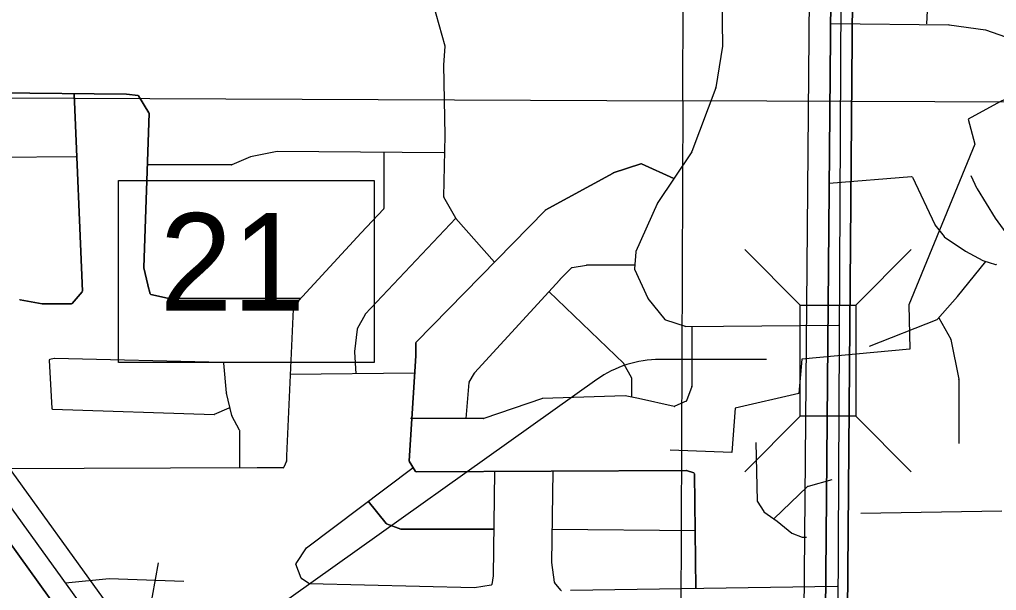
# Model space of a CAD drawing. Extents: x 408847 to 817539, y 923858 to 1151780.
# Drawn here: x 490719 to 495222, y 1058236 to 1060869 of the extents above; entities that cross this region are included whole.
import ezdxf

# ---------------------------------------------------------------- set-up
doc = ezdxf.new("R2010")
doc.units = 0
for name, color, linetype in [('Bridges', 7, 'Continuous'), ('County Route Divided Highway Outline and Fill', 7, 'Continuous'), ('County Routes Highway Center Lines', 7, 'Continuous'), ('Level 43', 7, 'Continuous'), ('Level 6', 7, 'Continuous'), ('Local Roads Improved', 7, 'Continuous'), ('Local Roads Paved', 7, 'Continuous'), ('Narrow River Creek and Branch and Slough', 7, 'Continuous'), ('Quad Borders', 7, 'Continuous'), ('Section Lines', 7, 'Continuous'), ('US Route Divided Highway Outline and Fill', 7, 'Continuous'), ('US Routes Highway Center Lines', 7, 'Continuous')]:
    doc.layers.add(name, color=color, linetype=linetype)

msp = doc.modelspace()

# ---------------------------------------------------------------- linework, layer by layer
at = {"layer": 'Bridges'}
for p, q in [((494317.6, 1059551.6), (494061.6, 1059807.6)), ((494573.6, 1059551.6), (494829.6, 1059807.6)), ((494317.6, 1059039.6), (494061.6, 1058783.6)), ((494573.6, 1059039.6), (494829.6, 1058783.6)), ((491295.8, 1058008.1), (491358.9, 1058364.5))]:
    msp.add_line(p, q, dxfattribs=at)
msp.add_lwpolyline([(494317.6, 1059039.6), (494317.6, 1059551.6), (494573.6, 1059551.6), (494573.6, 1059039.6)], close=True, dxfattribs=at)
at = {"layer": 'County Route Divided Highway Outline and Fill'}
for p, q in [((494505.3, 1078336), (494302.9, 1054340.5)), ((494605.3, 1078335.2), (494402.6, 1054313.9)), ((494705.3, 1078334.3), (494502.5, 1054302.3)), ((494502.5, 1054302.3), (494705.3, 1078334.3))]:
    msp.add_line(p, q, dxfattribs=at)
at = {"layer": 'County Routes Highway Center Lines'}
msp.add_line((494402.6, 1054313.9), (494605.3, 1078335.2), dxfattribs=at)
at = {"layer": 'Level 43'}
msp.add_lwpolyline([(491174.7, 1060126.5), (492354, 1060126.5), (492354, 1059287.4), (491174.7, 1059287.4)], close=True, dxfattribs=at)
at = {"layer": 'Level 6'}
for p, q in [((491636.7, 1057465.4), (489350, 1060629.5)), ((489186.2, 1060514.5), (491474.6, 1057348.2))]:
    msp.add_line(p, q, dxfattribs=at)
at = {"layer": 'Local Roads Improved'}
for p, q in [((493142.2, 1059989.3), (493454.9, 1060161)), ((493455.5, 1060161.3), (493582.8, 1060203.7)), ((493585.7, 1060203.6), (493734.9, 1060135.2)), ((492546.6, 1059381.4), (493141.3, 1059988.6)), ((492545.5, 1059318.9), (492545.5, 1059378.6)), ((492514.9, 1058834.2), (492545.5, 1059318.6)), ((492544.3, 1058785.6), (492515.5, 1058831.8)), ((492042, 1058433.6), (492533.1, 1058803.7)), ((493792.6, 1058789.9), (492547.7, 1058783.7)), ((492908.3, 1058785.5), (492902, 1058304.3)), ((493172.5, 1058365.9), (493178.9, 1058786.9)), ((493827.4, 1058778.5), (493793.9, 1058789.7)), ((493836.5, 1058245.1), (493830.2, 1058774.7)), ((492409.6, 1058544.8), (492326, 1058647.7)), ((492477.2, 1058519.6), (492411.3, 1058543.5)), ((492904.8, 1058519.3), (492478.6, 1058519.3)), ((491993.4, 1058361.1), (492041.1, 1058432.7)), ((493184.6, 1058274.5), (493172.5, 1058365.3)), ((492016.5, 1058293), (491993, 1058357.5)), ((492052.8, 1058267.8), (492018, 1058291.1)), ((492902, 1058303.8), (492896.3, 1058264)), ((493214.3, 1058237.9), (493185.5, 1058272.5)), ((492815.6, 1058248.8), (492054.9, 1058267.2)), ((492892.9, 1058260.6), (492816.3, 1058248.8)), ((494487.8, 1058254.9), (493258.5, 1058236.4))]:
    msp.add_line(p, q, dxfattribs=at)
for centre, start, end in [((493456.8, 1060157.5), 108.443, 118.7789), ((493584, 1060199.9), 65.3663, 108.443), ((493144.2, 1059985.8), 118.7789, 135.598), ((492549.5, 1059378.6), 135.598, 180), ((492541.5, 1059318.9), 356.3802, 0), ((492518.8, 1058834), 176.3802, 211.9934), ((492547.7, 1058787.7), 211.9934, 270.2824), ((493792.6, 1058785.9), 71.557, 90.2824), ((493826.2, 1058774.7), 0.69, 71.557), ((492412.7, 1058547.3), 219.0808, 250.0083), ((492478.6, 1058523.3), 250.0083, 270), ((492044.4, 1058430.4), 127.0016, 146.3223), ((491996.8, 1058358.9), 146.3223, 199.9745), ((493176.5, 1058365.8), 179.119, 187.5911), ((492020.2, 1058294.4), 199.9745, 236.2976), ((492898, 1058304.4), 351.8736, 359.2465), ((493188.6, 1058275), 187.5911, 219.7924), ((492055, 1058271.2), 236.2976, 268.6134), ((492815.7, 1058252.7), 268.6134, 278.7502), ((492892.3, 1058264.5), 278.7502, 351.8736), ((493217.3, 1058240.4), 219.7924, 270), ((493258.5, 1058240.4), 270, 270.8598)]:
    msp.add_arc(centre, 4, start, end, dxfattribs=at)
at = {"layer": 'Local Roads Paved'}
for p, q in [((493953.1, 1061126.6), (493959.2, 1060745.7)), ((493953.1, 1061126.6), (493959.2, 1060745.7)), ((494900.5, 1060849.3), (494914.3, 1061083.8)), ((492680.5, 1060746.1), (492625.5, 1060941.8)), ((494457.8, 1060849.9), (495003, 1060844.6)), ((495003.5, 1060844.6), (495170.9, 1060821.3)), ((495171.7, 1060821.1), (495344, 1060760.6)), ((492674.6, 1060659.5), (492680.7, 1060744.7)), ((493959.1, 1060745), (493928.5, 1060555.1)), ((493959.1, 1060745), (493928.5, 1060555.1)), ((492680.7, 1060333.5), (492674.6, 1060659.1)), ((491211.5, 1060524), (490081.9, 1060536.3)), ((490081.9, 1060536.3), (491211.5, 1060524)), ((491008.8, 1059615.5), (490971.6, 1060526.6)), ((490971.6, 1060526.6), (491008.8, 1059615.5)), ((491265.1, 1060518.1), (491211.9, 1060524)), ((491211.9, 1060524), (491265.1, 1060518.1)), ((493928.3, 1060554.4), (493818, 1060260)), ((493928.3, 1060554.4), (493818, 1060260)), ((491315.6, 1060438.9), (491268.1, 1060516.2)), ((491268.1, 1060516.2), (491315.6, 1060438.9)), ((491291.6, 1059725.1), (491316.2, 1060436.7)), ((491316.2, 1060436.7), (491291.6, 1059725.1)), ((492674.6, 1060051.6), (492680.7, 1060333.3)), ((491905.9, 1060259.5), (491783.8, 1060235.1)), ((492674.6, 1060253.4), (491906.7, 1060259.6)), ((492398, 1060255.6), (492398, 1059996.7)), ((493817.6, 1060259.2), (493658.2, 1060020)), ((493817.6, 1060259.2), (493658.2, 1060020)), ((490978.2, 1060235), (490076.7, 1060228.9)), ((491783, 1060234.8), (491698, 1060198.4)), ((491696.5, 1060198.1), (491307.9, 1060198.1)), ((493454.9, 1060161), (493142.2, 1059989.3)), ((493582.8, 1060203.7), (493455.5, 1060161.3)), ((493734.9, 1060135.2), (493585.7, 1060203.6)), ((494451.6, 1060114.5), (494830.5, 1060144.2)), ((494834.4, 1060141.9), (494937.5, 1059923.4)), ((495133.9, 1060088), (495106, 1060148.5)), ((495218, 1059952.4), (495134.1, 1060087.5)), ((492729.7, 1059952.5), (492675.1, 1060049.5)), ((492396.9, 1059994), (492293.5, 1059884.5)), ((493141.3, 1059988.6), (492546.6, 1059381.4)), ((493657.9, 1060019.4), (493560, 1059799)), ((493657.9, 1060019.4), (493560, 1059799)), ((492729.6, 1059952.6), (492312.3, 1059509.7)), ((492907.9, 1059750.3), (492730.2, 1059951.8)), ((495291.2, 1059851.6), (495218.1, 1059952.1)), ((494938, 1059922.7), (494980.4, 1059868.2)), ((492293.5, 1059884.5), (492004.8, 1059571.1)), ((494981.3, 1059867.3), (495078.9, 1059800.2)), ((493559.6, 1059797.7), (493553.6, 1059719.5)), ((493559.6, 1059797.7), (493553.6, 1059719.5)), ((495079.3, 1059799.9), (495158.6, 1059757.2)), ((495159.4, 1059756.9), (495218.4, 1059739.2)), ((491310, 1059644.7), (491291.7, 1059724.1)), ((491291.7, 1059724.1), (491310, 1059644.7)), ((493209.4, 1059669.3), (493263.8, 1059723.7)), ((493265.9, 1059724.8), (493331.9, 1059736.8)), ((493332.6, 1059736.9), (493554.9, 1059736.9)), ((493554, 1059717.5), (493614.8, 1059583.6)), ((493554, 1059717.5), (493614.8, 1059583.6)), ((495042.3, 1059591), (495172.9, 1059752.8)), ((492816.3, 1059239.1), (493209.3, 1059669.2)), ((491321.7, 1059603.9), (491310.1, 1059644.5)), ((491310.1, 1059644.5), (491321.7, 1059603.9)), ((490721.7, 1059576.7), (490824.1, 1059558.6)), ((490824.1, 1059558.6), (490721.7, 1059576.7)), ((490960.9, 1059559.9), (491007.8, 1059612.7)), ((491007.8, 1059612.7), (490960.9, 1059559.9)), ((491401.8, 1059583.3), (491324.7, 1059601.1)), ((491324.7, 1059601.1), (491401.8, 1059583.3)), ((492015.9, 1059583.2), (491402.7, 1059583.2)), ((491402.7, 1059583.2), (492015.9, 1059583.2)), ((493503.9, 1059282.3), (493159.4, 1059614.6)), ((493615.3, 1059582.8), (493694.2, 1059485.7)), ((493615.3, 1059582.8), (493694.2, 1059485.7)), ((494950.7, 1059487.2), (495042.2, 1059590.9)), ((490824.8, 1059558.6), (490957.9, 1059558.6)), ((490957.9, 1059558.6), (490824.8, 1059558.6)), ((491980, 1059532.8), (491949.3, 1058857.6)), ((492004.4, 1059570.6), (491980.6, 1059534.9)), ((492311.7, 1059508.9), (492275.4, 1059442.4)), ((494636.6, 1059363.4), (494949.1, 1059486.1)), ((494955.9, 1059493.1), (495011.2, 1059394.7)), ((492275, 1059440.9), (492262.8, 1059337.5)), ((493696, 1059484.4), (493786.5, 1059454.2)), ((493696, 1059484.4), (493786.5, 1059454.2)), ((493787.8, 1059454), (494493.9, 1059460.2)), ((493787.8, 1059454), (494493.9, 1059460.2)), ((493817.8, 1059454.3), (493817.8, 1059178)), ((492545.5, 1059378.6), (492545.5, 1059318.9)), ((495011.6, 1059393.6), (495048.3, 1059210.1)), ((490879.3, 1059306.3), (490858.4, 1059301.1)), ((490879.3, 1059306.3), (490858.4, 1059301.1)), ((491656.8, 1059288.1), (490880.3, 1059306.4)), ((491656.8, 1059288.1), (490880.3, 1059306.4)), ((492262.8, 1059336.8), (492269.1, 1059235.9)), ((492545.5, 1059318.6), (492514.9, 1058834.2)), ((490855.4, 1059297), (490867.3, 1059076.4)), ((490855.4, 1059297), (490867.3, 1059076.4)), ((491672.7, 1059146.8), (491660.7, 1059284.4)), ((491672.7, 1059146.8), (491660.7, 1059284.4)), ((493540.8, 1059215.1), (493504.7, 1059281.3)), ((492539.4, 1059238.8), (491966.3, 1059232.8)), ((492791.8, 1059196.5), (492815.7, 1059238.4)), ((492777.5, 1059029.7), (492791.3, 1059194.9)), ((493541.2, 1059128.1), (493541.2, 1059213.2)), ((493817.6, 1059176.6), (493793.8, 1059111.2)), ((495048.4, 1059209.3), (495048.4, 1058914.5)), ((491697.2, 1059042.5), (491672.8, 1059146.3)), ((491697.2, 1059042.5), (491672.8, 1059146.3)), ((493510, 1059134.2), (493130, 1059122)), ((493571.9, 1059122), (493511, 1059134.2)), ((491685.3, 1059079.1), (491688.1, 1059081)), ((491685.3, 1059079.1), (491688.1, 1059081)), ((493128.9, 1059121.8), (492859.6, 1059029.9)), ((493736.6, 1059085.3), (493572, 1059121.9)), ((493791.7, 1059109), (493739.1, 1059085.6)), ((490871.2, 1059072.6), (491616.5, 1059048.2)), ((490871.2, 1059072.6), (491616.5, 1059048.2)), ((491618.2, 1059048.5), (491684.7, 1059078.8)), ((491618.2, 1059048.5), (491684.7, 1059078.8)), ((491733.7, 1058975.3), (491697.5, 1059041.5)), ((491733.7, 1058975.3), (491697.5, 1059041.5)), ((492858.3, 1059029.7), (492520.9, 1059029.7)), ((491734.2, 1058801.9), (491734.2, 1058973.3)), ((491734.2, 1058801.9), (491734.2, 1058973.3)), ((494112.9, 1058919), (494119, 1058649.5)), ((491949.3, 1058857.4), (491949.3, 1058833.7)), ((491949, 1058832.2), (491938, 1058804.7)), ((492515.5, 1058831.8), (492544.3, 1058785.6)), ((491814.1, 1058802.2), (490550.9, 1058797.2)), ((491934.3, 1058802.2), (491814.1, 1058802.2)), ((492042, 1058433.6), (492533.1, 1058803.7)), ((492547.7, 1058783.7), (493792.6, 1058789.9)), ((492908.3, 1058785.5), (492902, 1058304.3)), ((493172.5, 1058365.9), (493178.9, 1058786.9)), ((493793.9, 1058789.7), (493827.4, 1058778.5)), ((493830.2, 1058774.7), (493836.5, 1058245.1)), ((494463.2, 1058746.8), (494353.5, 1058716.4)), ((494351.8, 1058715.4), (494196.4, 1058566.6)), ((492326, 1058647.7), (492409.6, 1058544.8)), ((494119.6, 1058647.5), (494149.3, 1058599.9)), ((494150.4, 1058598.8), (494211.1, 1058556.3)), ((494597.3, 1058592.1), (495246.7, 1058603.3)), ((492411.3, 1058543.5), (492477.2, 1058519.6)), ((494211.3, 1058556.1), (494278.3, 1058501.3)), ((492478.6, 1058519.3), (492904.8, 1058519.3)), ((493174.8, 1058519.4), (493833.3, 1058513)), ((494279.4, 1058500.6), (494327.3, 1058482.7)), ((494328.7, 1058482.4), (494346.4, 1058482.4)), ((491993.4, 1058361.1), (492041.1, 1058432.7)), ((493184.6, 1058274.5), (493172.5, 1058365.3)), ((492016.5, 1058293), (491993, 1058357.5)), ((490930.9, 1058271.3), (491131.5, 1058291.8)), ((491132.1, 1058291.8), (491476, 1058279.5)), ((492052.8, 1058267.8), (492018, 1058291.1)), ((492902, 1058303.8), (492896.3, 1058264)), ((493214.3, 1058237.9), (493185.5, 1058272.5)), ((492815.6, 1058248.8), (492054.9, 1058267.2)), ((492892.9, 1058260.6), (492816.3, 1058248.8)), ((494487.8, 1058254.9), (493258.5, 1058236.4))]:
    msp.add_line(p, q, dxfattribs=at)
for centre, start, end in [((495002.9, 1060840.6), 82.0892, 89.4435), ((495170.4, 1060817.4), 70.6327, 82.0892), ((492676.7, 1060745), 355.9163, 15.7017), ((493955.2, 1060745.7), 350.8418, 0.9236), ((493955.2, 1060745.7), 350.8418, 0.9236), ((492678.6, 1060659.2), 175.9163, 181.0804), ((491211.5, 1060520), 83.6569, 89.377), ((491211.5, 1060520), 83.6569, 89.377), ((493924.6, 1060555.8), 339.4527, 350.8418), ((493924.6, 1060555.8), 339.4527, 350.8418), ((491264.7, 1060514.1), 31.5956, 83.6569), ((491264.7, 1060514.1), 31.5956, 83.6569), ((491312.2, 1060436.8), 358.026, 31.5956), ((491312.2, 1060436.8), 358.026, 31.5956), ((492676.7, 1060333.4), 358.7552, 1.0804), ((491906.7, 1060255.6), 89.5414, 101.3151), ((493814.2, 1060261.4), 326.3223, 339.4527), ((493814.2, 1060261.4), 326.3223, 339.4527), ((491784.5, 1060231.1), 101.3151, 113.2083), ((491696.5, 1060202.1), 270, 293.2083), ((493456.8, 1060157.5), 108.443, 118.7789), ((493584, 1060199.9), 65.3663, 108.443), ((494830.8, 1060140.2), 25.2674, 94.4867), ((495137.5, 1060089.6), 204.765, 211.8155), ((492678.6, 1060051.5), 178.7552, 209.3463), ((492394, 1059996.7), 316.6499, 0), ((493144.2, 1059985.8), 118.7789, 135.598), ((493661.5, 1060017.8), 146.3223, 156.0474), ((493661.5, 1060017.8), 146.3223, 156.0474), ((492733.2, 1059954.4), 209.3463, 221.4104), ((495221.4, 1059954.5), 211.8155, 216.0147), ((494941.2, 1059925.1), 205.2674, 217.862), ((492296.4, 1059881.7), 136.6499, 137.3506), ((494983.5, 1059870.6), 217.862, 235.479), ((495081.2, 1059803.5), 235.479, 241.6881), ((493563.6, 1059797.4), 156.0474, 175.6033), ((493563.6, 1059797.4), 156.0474, 175.6033), ((495160.5, 1059760.7), 241.6881, 253.2934), ((491295.6, 1059725), 178.026, 192.9888), ((491295.6, 1059725), 178.026, 192.9888), ((493266.6, 1059720.9), 100.3095, 135.0133), ((493332.6, 1059732.9), 90, 100.3095), ((493557.6, 1059719.2), 175.6033, 204.4339), ((493557.6, 1059719.2), 175.6033, 204.4339), ((495219.5, 1059743), 253.2934, 310.9276), ((493212.2, 1059666.5), 135.0133, 137.5771), ((491313.9, 1059645.6), 192.9888, 195.9383), ((491313.9, 1059645.6), 192.9888, 195.9383), ((490722.4, 1059580.6), 213.6777, 259.9875), ((490722.4, 1059580.6), 213.6777, 259.9875), ((491004.8, 1059615.3), 318.3797, 2.3362), ((491004.8, 1059615.3), 318.3797, 2.3362), ((491325.6, 1059605), 195.9383, 256.9995), ((491325.6, 1059605), 195.9383, 256.9995), ((491402.7, 1059587.2), 256.9995, 270), ((491402.7, 1059587.2), 256.9995, 270), ((493618.4, 1059585.3), 204.4339, 219.0808), ((493618.4, 1059585.3), 204.4339, 219.0808), ((495039.2, 1059593.6), 318.5896, 321.0855), ((490824.8, 1059562.6), 259.9875, 270), ((490824.8, 1059562.6), 259.9874, 270), ((490957.9, 1059562.6), 270, 318.3797), ((490957.9, 1059562.6), 270, 318.3797), ((491984, 1059532.7), 146.3223, 177.3986), ((492007.8, 1059568.4), 137.3506, 146.3223), ((492315.2, 1059507), 136.698, 151.4008), ((493697.3, 1059488.2), 219.0808, 251.557), ((493697.3, 1059488.2), 219.0808, 251.557), ((494947.7, 1059489.8), 291.422, 318.5896), ((492278.9, 1059440.5), 151.4008, 173.2933), ((493787.7, 1059458), 251.557, 270.4984), ((493787.7, 1059458), 251.557, 270.4984), ((492549.5, 1059378.6), 135.598, 180), ((495007.7, 1059392.8), 11.3048, 29.3463), ((490880.3, 1059302.4), 88.6462, 104.0425), ((490880.3, 1059302.4), 88.6462, 104.0425), ((492266.8, 1059337.1), 173.2933, 183.5747), ((492541.5, 1059318.9), 356.3802, 0), ((490859.4, 1059297.2), 104.0425, 183.0926), ((490859.4, 1059297.2), 104.0425, 183.0926), ((491656.7, 1059284.1), 4.9674, 88.6462), ((491656.7, 1059284.1), 4.9674, 88.6462), ((493501.1, 1059279.4), 28.5992, 46.0283), ((492819.2, 1059236.4), 137.5771, 150.2666), ((493537.2, 1059213.2), 0, 28.5992), ((492795.3, 1059194.5), 150.2666, 175.2386), ((493813.8, 1059178), 340.0255, 0), ((495044.4, 1059209.3), 0, 11.3048), ((491676.7, 1059147.2), 184.9674, 193.2346), ((491676.7, 1059147.2), 184.9674, 193.2346), ((493510.2, 1059130.2), 78.6849, 91.8485), ((493130.1, 1059118), 91.8485, 108.8329), ((493571.1, 1059118), 77.4655, 78.6849), ((493737.5, 1059089.2), 257.4655, 293.9724), ((493790.1, 1059112.6), 293.9724, 340.0255), ((490871.3, 1059076.6), 183.0926, 268.1212), ((490871.3, 1059076.6), 183.0926, 268.1212), ((491616.6, 1059052.2), 268.1212, 294.454), ((491616.6, 1059052.2), 268.1212, 294.454), ((491683, 1059082.4), 294.454, 303.7024), ((491683, 1059082.4), 294.454, 303.7024), ((491701.1, 1059043.4), 193.2346, 208.5992), ((491701.1, 1059043.4), 193.2346, 208.5992), ((492858.3, 1059033.7), 270, 288.8329), ((491730.2, 1058973.3), 0, 28.5992), ((491730.2, 1058973.3), 0, 28.5992), ((491953.3, 1058857.4), 177.3986, 180), ((491945.3, 1058833.7), 338.2078, 0), ((492518.8, 1058834), 176.3802, 211.9934), ((491814.1, 1058798.2), 90, 90.2275), ((491934.3, 1058806.2), 270, 338.2078), ((492547.7, 1058787.7), 211.9934, 270.2824), ((493792.6, 1058785.9), 71.557, 90.2824), ((493826.2, 1058774.7), 0.69, 71.557), ((494354.6, 1058712.5), 105.531, 133.7403), ((494123, 1058649.6), 181.3013, 211.9934), ((494152.7, 1058602.1), 211.9934, 234.9954), ((492412.7, 1058547.3), 219.0808, 250.0083), ((494208.8, 1058553), 50.6975, 54.9954), ((492478.6, 1058523.3), 250.0083, 270), ((494280.8, 1058504.4), 230.6975, 249.4352), ((494328.7, 1058486.4), 249.4352, 270), ((492044.4, 1058430.4), 127.0016, 146.3223), ((491996.8, 1058358.9), 146.3223, 199.9745), ((493176.5, 1058365.8), 179.119, 187.5911), ((491131.9, 1058287.8), 87.9536, 95.829), ((492020.2, 1058294.4), 199.9745, 236.2976), ((492898, 1058304.4), 351.8736, 359.2465), ((493188.6, 1058275), 187.5911, 219.7924), ((492055, 1058271.2), 236.2976, 268.6134), ((492815.7, 1058252.7), 268.6134, 278.7502), ((492892.3, 1058264.5), 278.7502, 351.8736), ((493217.3, 1058240.4), 219.7924, 270), ((493258.5, 1058240.4), 270, 270.8598)]:
    msp.add_arc(centre, 4, start, end, dxfattribs=at)
at = {"layer": 'Narrow River Creek and Branch and Slough'}
for p, q in [((494162.8, 1059301.5), (493670.2, 1059301.5)), ((493380.3, 1059208.9), (489589.5, 1056511.9))]:
    msp.add_line(p, q, dxfattribs=at)
msp.add_lwpolyline([(495701.6, 1060672.2), (495441.2, 1060580.6), (495241.4, 1060491.4), (495091.5, 1060409.7), (495122.2, 1060293.9), (494818.4, 1059552.5), (494823.1, 1059349.1), (494324.9, 1059302.8), (494310.7, 1059144.6), (494018.4, 1059076.8), (494002.1, 1058872.5), (493717.9, 1058882.8)], dxfattribs=at)
msp.add_arc((493670.2, 1058801.5), 500, 90.0005, 125.4302, dxfattribs=at)
msp.add_spline([(488826.1, 1060521.4), (488798.1, 1060645.5), (488830.1, 1060765.7), (488946.2, 1060903.8), (489164.5, 1061070), (489420.8, 1061236.2), (489727.1, 1061434.4), (489941.3, 1061634.6), (490069.5, 1061818.8), (490181.6, 1061981), (490421.9, 1062183.2), (490554, 1062275.4), (490792.3, 1062327.4), (490994.5, 1062327.4), (491276.8, 1062297.4), (491541.1, 1062373.5), (491841.4, 1062495.6), (491999.6, 1062585.7), (492169.8, 1062661.8), (492388, 1062755.9), (492614.3, 1062763.9), (492970.7, 1062773.9), (493283, 1062822), (493589.4, 1062932.1), (493675.4, 1062966.1), (493855.6, 1063058.2)], degree=3, dxfattribs=at)
at = {"layer": 'Quad Borders'}
for p, q in [((493776.8, 1060493), (493958.9, 1105932.5)), ((493776.8, 1060493), (493958.9, 1105932.5)), ((453162.9, 1060675.2), (493776.8, 1060493)), ((453264.3, 1060674.7), (493776.8, 1060493)), ((493776.8, 1060493), (493595.5, 1015054.2)), ((505451.3, 1060452.2), (493776.8, 1060493))]:
    msp.add_line(p, q, dxfattribs=at)
at = {"layer": 'Section Lines'}
msp.add_line((494487.3, 1056871.9), (494510.6, 1061829.6), dxfattribs=at)
at = {"layer": 'US Route Divided Highway Outline and Fill'}
for p, q in [((491474.6, 1057348.2), (489186.2, 1060514.5)), ((489186.2, 1060514.5), (491474.6, 1057348.2))]:
    msp.add_line(p, q, dxfattribs=at)
at = {"layer": 'US Routes Highway Center Lines'}
msp.add_line((491555.7, 1057406.8), (489272.2, 1060566.7), dxfattribs=at)

# ---------------------------------------------------------------- texts
at = {"layer": 'Level 43'}
msp.add_text('21', height=450, rotation=0.0005, dxfattribs=at).set_placement((491365, 1059525.9))

doc.saveas('drawing.dxf')
